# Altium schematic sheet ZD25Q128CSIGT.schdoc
size 127 x 101 mm
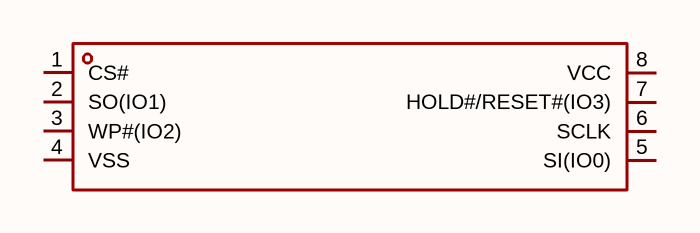
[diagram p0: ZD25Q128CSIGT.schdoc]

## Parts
U?  zd25q128csigt  [SOP-8_L5.3-W5.3-P1.27-LS7.9-BL]  (value not drawn)

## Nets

Not connected (* = marked no-connect by the designer): U? 1(CS#) 2(SO(IO1)) 3(WP#(IO2)) 4(VSS) 5(SI(IO0)) 6(SCLK) 7(HOLD#/RESET#(IO3)) 8(VCC)

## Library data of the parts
U? = zd25q128csigt: 接口类型:SPI;存储容量:-;时钟频率(fc):133MHz;; Manufacturer: Zetta(澜智); AddInBom: yes; ModelId: 72eaeed142424588879d6a198b07ab72; ModelTransform: 207.67675,311.023,0,0,0,0,0,0,0; Interface: SPI; Clock Frequency: 133MHz; Voltage - Supply: 2.7V~3.6V; Page Programming Time (Tpp): 500us; Data Retention - TDR (Year): 20年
